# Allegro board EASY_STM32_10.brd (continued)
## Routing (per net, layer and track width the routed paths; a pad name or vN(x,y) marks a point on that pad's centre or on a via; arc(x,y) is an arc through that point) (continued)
N14990153: length 5.2
  TOP w0.175: U8.6 16.8,16.5 16.8,18.6 17.6,19.4 R67.1
N14990191: length 3
  TOP w0.175: R65.2 19.1,19.9 17.8,18.6 U8.3
N14990197: length 4.1
  TOP w0.2: R60.2 R61.2 16.1,17.8 U8.5
N14990201: length 6.5
  TOP w0.175: R64.2 10.19,19.99 11,20.8 12.29,20.8 R63.2
  TOP w0.2: U8.7 13.8,18.8 13.1,19.5 R63.2
N15001570: length 1.7
  TOP w0.6: D3.A R70.2

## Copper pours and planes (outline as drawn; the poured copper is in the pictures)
+3V3 on TOP: 23.3,55.3 23.3,56.5 23.6,56.8 24.1,56.8 24.7,56.2 27,56.2 27,55.3
+3V3 on TOP: 9.5,59.3 10.3,59.3 10.3,57.3 12.1,57.3 12.1,55.6 12.8,54.9 14,54.9 14.6,54.3 14.6,52.6 15.7,52.6 15.7,53.2 16.2,53.2 16.2,52.6 17.8,52.6 18.9,51.5 18.9,50.8 10.8,50.8 10.1,50.1 10.1,48.3 9.7,47.9 9.7,46.8 9,46.8 9,49.2 6.8,51.4 6.8,52.8 8.6,54.6 8.6,57.3 9.5,57.3
+3V3 on BOTTOM: 11.9,54.7 19.5,54.7 24.2,59.4 27,59.4 27.3,59.1 27.3,52.5 26.8,52 11.9,52
+5V on TOP: 16.3,60.7 17.9,60.7 17.9,58.6 17.8,58.5 15.9,58.5 15.2,57.8 14.7,57.8 14.4,58.1 14.4,59.4 14.8,59.8 15.8,59.8 16.2,60.2 16.2,60.6
+5V on TOP: 6.7,61.9 6.7,57.8 9,57.8 9,61.9
+5V on BOTTOM: 8,59.8 8,57.8 15.5,57.8 15.5,59.8
GND on TOP: 11.4,41.8 10.6,41.8 10.5,41.7 10.5,41.2 8.8,39.5 8.8,36.1 11.8,33.1 11.8,30.1 12.5,29.4 12.5,26.8 15.9,26.8 15.9,28.4 14.8,28.4 13.1,30.1 13.1,31.9 13.7,32.5 15,32.5 15.1,32.6 15.1,33.2 15,33.3 13.5,33.3 10,36.8 10,38.6 10.6,39.2 11.4,39.2 11.5,39.3 11.5,41.7
GND on TOP: 35.1,61.9 35.1,59.4 35.9,59.4 35.9,60.3 36.4,60.3 36.7,60.6 36.7,60.9 37.5,60.9 37.5,61.6 37.2,61.9
GND on TOP: 6.8,67.3 6.8,64.6 9,64.6 9,67.3
GND on TOP: 12.9,58.6 11.8,58.6 11.8,60 11,60 11,60.8 13.2,60.8 13.6,61.2 15.2,61.2 15.5,60.9 15.5,60.5 15.2,60.2 14.5,60.2
GND on BOTTOM: 0.2,76.1 2.9,76.1 3.9,77.1 3.9,79.8 47.1,79.8 47.1,77.1 48.1,76.1 50.8,76.1 50.8,3.9 48.1,3.9 47.1,2.9 47.1,0.2 3.9,0.2 3.9,2.9 2.9,3.9 0.2,3.9 ; 1 cut-out
Net_5 on BOTTOM (solid shape): 11.86,6.88 12.49,6.88 12.49,6.38 11.86,6.38 11.86,5.38 12.49,5.38 12.49,4.88 10.11,4.88 10.11,5.38 11.36,5.38 11.36,6.12 10.61,5.38 10.11,5.38 10.11,5.62 10.99,6.5 10.11,7.38 10.11,8.12 11.36,6.88 11.36,8.12 11.86,8.12

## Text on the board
Ref Des/Silkscreen Top: +3V3 | +5V | PA15 | PA14 | PC10 | PC11 | PC12 | VBAT | PC13 | NRST | VSSA | VDDA | GND | PD2 | PB3 | PB4 | PB5 | PB6 | PB7 | PB8 | PB9 | PC0 | PC1 | PC2 | PC3 | PA0 | PA1 | PA2 | PA13 | PA12 | PA11 | PA10 | PA9 | PA8 | PC9 | PC8 | PC7 | PC6 | PB15 | PB14 | PB13 | PB12 | PB11 | PB10 | PB2 | PB1 | PB0 | PC5 | PC4 | PA7 | PA6 | PA5 | PA4 | DBGU | 14102011 | SPEED UP YOUR INNOVATIONS | BOOT0 | BOOT1 | kamejoko80@yahoo.com | COPY RIGHT @ 2011 | USR_LED | PWR_LED | USB | EASY_STM32 | RESET
DIMENSION: FIGURE | SIZE | 0.508 | 0.8 | 0.9 | 0.914 | 1.0 | 3.0 | DRILL CHART: TOP to BOTTOM | ALL UNITS ARE IN MILLIMETERS | PLATED | NON-PLATED | QTY | 208 | 14 | 60 | 4 | 2
